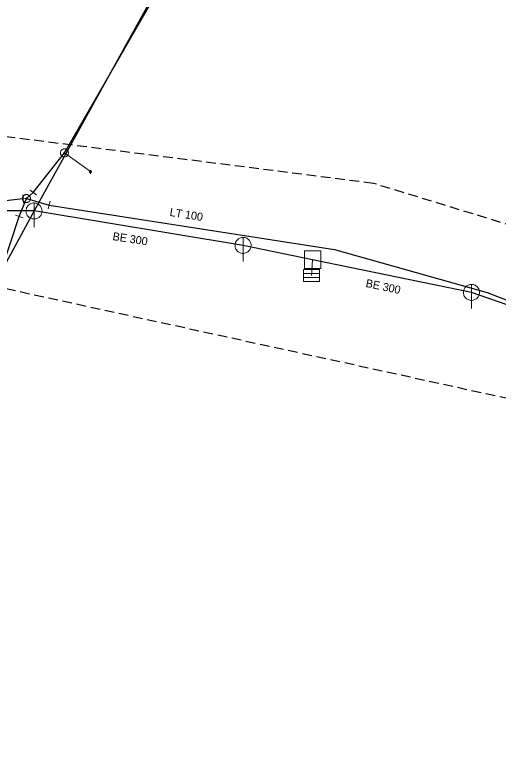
# Model space of a CAD drawing. Extents: x -687387 to -687009, y -972789 to -972578.
# Drawn here: x -687141.5 to -687081.2, y -972744.5 to -972651.8 of the extents above; entities that cross this region are included whole.
import ezdxf

# ---------------------------------------------------------------- set-up
doc = ezdxf.new("R2010")
doc.units = 0
doc.header["$LTSCALE"] = 0.4
doc.linetypes.add('MEDIUM_DASHED', pattern=[4.5, 3, -1.5])
doc.layers.add('1', color=7, linetype='Continuous')
for name, color, linetype, lineweight in [('11', 7, 'Continuous', 13), ('14', 7, 'Continuous', 25), ('17', 7, 'Continuous', 25), ('22', 7, 'Continuous', 13), ('34', 7, 'Continuous', 13), ('47', 7, 'Continuous', 13), ('63', 7, 'MEDIUM_DASHED', 25), ('9', 7, 'Continuous', 13)]:
    doc.layers.add(name, color=color, linetype=linetype, lineweight=lineweight)

msp = doc.modelspace()

# ---------------------------------------------------------------- linework, layer by layer
at = {"layer": '11'}
msp.add_line((-687104.473, -972684.315), (-687104.363, -972682.335), dxfattribs=at)
at = {"layer": '14', "lineweight": 13}
for p, q in [((-687132.046, -972671.358), (-687135.293, -972669.02)), ((-687140.419, -972674.734), (-687140.013, -972674.707))]:
    msp.add_line(p, q, dxfattribs=at)
at = {"layer": '14'}
for p, q in [((-687139.074, -972676.263), (-687177.589, -972676.2)), ((-687113.022, -972680.553), (-687139.074, -972676.263)), ((-687104.363, -972682.335), (-687113.022, -972680.553)), ((-687084.556, -972686.414), (-687104.363, -972682.335)), ((-687076.354, -972689.285), (-687084.556, -972686.414))]:
    msp.add_line(p, q, dxfattribs=at)
for points in [[(-687109.862, -972623.402), (-687127.339, -972655.027), (-687139.074, -972676.263)], [(-687139.074, -972676.263), (-687143.356, -972684.136), (-687154.625, -972704.857), (-687159.462, -972713.752)]]:
    msp.add_lwpolyline(points, dxfattribs=at)
at = {"layer": '17'}
for p, q in [((-687139.168, -972673.949), (-687135.293, -972669.02)), ((-687140.013, -972674.707), (-687137.189, -972675.528))]:
    msp.add_line(p, q, dxfattribs=at)
for points in [[(-687135.293, -972669.02), (-687122.188, -972646.265), (-687104.355, -972614.76), (-687083.126, -972578.198)], [(-687175.65, -972744.492), (-687175.739, -972743.912), (-687173.329, -972740.07), (-687156.205, -972711.508), (-687144.176, -972686.673), (-687140.919, -972676.959), (-687140.013, -972674.707), (-687139.168, -972673.949)], [(-687140.419, -972674.734), (-687161.655, -972677.153), (-687161.956, -972677.145), (-687194.054, -972677.975), (-687218.609, -972681.129), (-687239.739, -972685.945)], [(-687137.189, -972675.528), (-687101.625, -972681.079), (-687082.6, -972686.438), (-687052.118, -972698.285)]]:
    msp.add_lwpolyline(points, dxfattribs=at)
at = {"layer": '22'}
for p, q in [((-687139.074, -972678.263), (-687139.073, -972675.263)), ((-687113.022, -972682.553), (-687113.021, -972679.553)), ((-687105.484, -972684.058), (-687103.484, -972684.058)), ((-687105.484, -972684.558), (-687103.484, -972684.558)), ((-687084.556, -972688.414), (-687084.555, -972685.414))]:
    msp.add_line(p, q, dxfattribs=at)
for points in [[(-687138.074, -972676.263), (-687138.079, -972676.154), (-687138.097, -972676.046), (-687138.127, -972675.94), (-687138.167, -972675.839), (-687138.219, -972675.742), (-687138.281, -972675.652), (-687138.353, -972675.569), (-687138.433, -972675.495), (-687138.521, -972675.429), (-687138.615, -972675.374), (-687138.715, -972675.329), (-687138.82, -972675.296), (-687138.927, -972675.274), (-687139.036, -972675.264), (-687139.146, -972675.266), (-687139.254, -972675.28), (-687139.361, -972675.305), (-687139.464, -972675.342), (-687139.562, -972675.391), (-687139.654, -972675.449), (-687139.74, -972675.518), (-687139.817, -972675.595), (-687139.886, -972675.681), (-687139.945, -972675.773), (-687139.993, -972675.871), (-687140.03, -972675.974), (-687140.056, -972676.081), (-687140.07, -972676.189), (-687140.073, -972676.299), (-687140.063, -972676.408), (-687140.042, -972676.515), (-687140.008, -972676.619), (-687139.964, -972676.719), (-687139.909, -972676.814), (-687139.843, -972676.902), (-687139.769, -972676.982), (-687139.686, -972677.054), (-687139.596, -972677.116), (-687139.5, -972677.168), (-687139.398, -972677.209), (-687139.293, -972677.239), (-687139.185, -972677.257), (-687139.075, -972677.263), (-687138.966, -972677.257), (-687138.858, -972677.239), (-687138.753, -972677.21), (-687138.651, -972677.169), (-687138.554, -972677.117), (-687138.464, -972677.055), (-687138.381, -972676.984), (-687138.306, -972676.904), (-687138.241, -972676.816), (-687138.185, -972676.722), (-687138.141, -972676.622), (-687138.107, -972676.518), (-687138.085, -972676.41), (-687138.075, -972676.301)], [(-687112.022, -972680.553), (-687112.027, -972680.444), (-687112.045, -972680.336), (-687112.075, -972680.23), (-687112.115, -972680.129), (-687112.167, -972680.032), (-687112.229, -972679.942), (-687112.301, -972679.859), (-687112.381, -972679.785), (-687112.469, -972679.719), (-687112.563, -972679.664), (-687112.663, -972679.619), (-687112.768, -972679.586), (-687112.875, -972679.564), (-687112.984, -972679.554), (-687113.094, -972679.556), (-687113.202, -972679.57), (-687113.309, -972679.595), (-687113.412, -972679.632), (-687113.51, -972679.681), (-687113.602, -972679.739), (-687113.688, -972679.808), (-687113.765, -972679.885), (-687113.834, -972679.971), (-687113.893, -972680.063), (-687113.941, -972680.161), (-687113.978, -972680.264), (-687114.004, -972680.371), (-687114.018, -972680.479), (-687114.021, -972680.589), (-687114.011, -972680.698), (-687113.99, -972680.805), (-687113.956, -972680.909), (-687113.912, -972681.009), (-687113.857, -972681.104), (-687113.791, -972681.192), (-687113.717, -972681.272), (-687113.634, -972681.344), (-687113.544, -972681.406), (-687113.448, -972681.458), (-687113.346, -972681.499), (-687113.241, -972681.529), (-687113.133, -972681.547), (-687113.023, -972681.553), (-687112.914, -972681.547), (-687112.806, -972681.529), (-687112.701, -972681.5), (-687112.599, -972681.459), (-687112.502, -972681.407), (-687112.412, -972681.345), (-687112.329, -972681.274), (-687112.254, -972681.194), (-687112.189, -972681.106), (-687112.133, -972681.012), (-687112.089, -972680.912), (-687112.055, -972680.808), (-687112.033, -972680.7), (-687112.023, -972680.591)], [(-687105.343, -972681.245), (-687103.31, -972681.245), (-687103.31, -972683.438), (-687105.343, -972683.438)], [(-687105.484, -972683.558), (-687103.484, -972683.558), (-687103.484, -972685.058), (-687105.484, -972685.058)], [(-687083.556, -972686.414), (-687083.561, -972686.305), (-687083.579, -972686.197), (-687083.609, -972686.091), (-687083.649, -972685.99), (-687083.701, -972685.893), (-687083.763, -972685.803), (-687083.835, -972685.72), (-687083.915, -972685.646), (-687084.003, -972685.58), (-687084.097, -972685.525), (-687084.197, -972685.48), (-687084.302, -972685.447), (-687084.409, -972685.425), (-687084.518, -972685.415), (-687084.628, -972685.417), (-687084.736, -972685.431), (-687084.843, -972685.456), (-687084.946, -972685.493), (-687085.044, -972685.542), (-687085.136, -972685.6), (-687085.222, -972685.669), (-687085.299, -972685.746), (-687085.368, -972685.832), (-687085.427, -972685.924), (-687085.475, -972686.022), (-687085.512, -972686.125), (-687085.538, -972686.232), (-687085.552, -972686.34), (-687085.555, -972686.45), (-687085.545, -972686.559), (-687085.524, -972686.666), (-687085.49, -972686.77), (-687085.446, -972686.87), (-687085.391, -972686.965), (-687085.325, -972687.053), (-687085.251, -972687.133), (-687085.168, -972687.205), (-687085.078, -972687.267), (-687084.982, -972687.319), (-687084.88, -972687.36), (-687084.775, -972687.39), (-687084.667, -972687.408), (-687084.557, -972687.414), (-687084.448, -972687.408), (-687084.34, -972687.39), (-687084.235, -972687.361), (-687084.133, -972687.32), (-687084.036, -972687.268), (-687083.946, -972687.206), (-687083.863, -972687.135), (-687083.788, -972687.055), (-687083.723, -972686.967), (-687083.667, -972686.873), (-687083.623, -972686.773), (-687083.589, -972686.669), (-687083.567, -972686.561), (-687083.557, -972686.452)]]:
    msp.add_lwpolyline(points, close=True, dxfattribs=at)
at = {"layer": '34'}
for p, q in [((-687139.567, -972673.648), (-687138.768, -972674.249)), ((-687140.454, -972674.235), (-687140.384, -972675.232)), ((-687137.054, -972675.046), (-687137.324, -972676.009)), ((-687141.393, -972676.8), (-687140.444, -972677.118))]:
    msp.add_line(p, q, dxfattribs=at)
at = {"layer": '47'}
for points in [[(-687135.045, -972668.585), (-687135.091, -972668.562), (-687135.141, -972668.543), (-687135.191, -972668.531), (-687135.242, -972668.522), (-687135.295, -972668.52), (-687135.348, -972668.523), (-687135.399, -972668.532), (-687135.449, -972668.546), (-687135.498, -972668.564), (-687135.545, -972668.588), (-687135.589, -972668.617), (-687135.629, -972668.65), (-687135.666, -972668.687), (-687135.698, -972668.728), (-687135.727, -972668.772), (-687135.75, -972668.818), (-687135.769, -972668.868), (-687135.782, -972668.919), (-687135.79, -972668.969), (-687135.792, -972669.022), (-687135.789, -972669.075), (-687135.781, -972669.127), (-687135.767, -972669.177), (-687135.749, -972669.226), (-687135.724, -972669.272), (-687135.695, -972669.316), (-687135.662, -972669.357), (-687135.625, -972669.393), (-687135.584, -972669.425), (-687135.54, -972669.454), (-687135.494, -972669.477), (-687135.444, -972669.496), (-687135.394, -972669.51), (-687135.343, -972669.517), (-687135.29, -972669.519), (-687135.238, -972669.517), (-687135.186, -972669.509), (-687135.135, -972669.495), (-687135.086, -972669.476), (-687135.04, -972669.451), (-687134.996, -972669.422), (-687134.956, -972669.39), (-687134.919, -972669.352), (-687134.887, -972669.311), (-687134.858, -972669.267), (-687134.835, -972669.221), (-687134.816, -972669.171), (-687134.803, -972669.121), (-687134.795, -972669.07), (-687134.793, -972669.017), (-687134.795, -972668.965), (-687134.804, -972668.914), (-687134.818, -972668.863), (-687134.837, -972668.814), (-687134.861, -972668.767), (-687134.89, -972668.723), (-687134.923, -972668.684), (-687134.96, -972668.646), (-687135.001, -972668.614)], [(-687135.252, -972668.948), (-687135.26, -972668.944), (-687135.268, -972668.942), (-687135.276, -972668.939), (-687135.284, -972668.938), (-687135.293, -972668.938), (-687135.302, -972668.938), (-687135.31, -972668.939), (-687135.318, -972668.942), (-687135.326, -972668.945), (-687135.334, -972668.949), (-687135.341, -972668.954), (-687135.348, -972668.959), (-687135.354, -972668.965), (-687135.359, -972668.971), (-687135.364, -972668.979), (-687135.368, -972668.987), (-687135.37, -972668.995), (-687135.373, -972669.003), (-687135.374, -972669.011), (-687135.374, -972669.02), (-687135.374, -972669.029), (-687135.373, -972669.037), (-687135.37, -972669.045), (-687135.367, -972669.054), (-687135.363, -972669.061), (-687135.358, -972669.068), (-687135.353, -972669.075), (-687135.347, -972669.081), (-687135.341, -972669.086), (-687135.333, -972669.091), (-687135.325, -972669.095), (-687135.317, -972669.097), (-687135.309, -972669.1), (-687135.301, -972669.101), (-687135.292, -972669.101), (-687135.284, -972669.101), (-687135.275, -972669.1), (-687135.267, -972669.097), (-687135.258, -972669.094), (-687135.251, -972669.09), (-687135.244, -972669.085), (-687135.237, -972669.08), (-687135.231, -972669.074), (-687135.226, -972669.068), (-687135.221, -972669.06), (-687135.217, -972669.052), (-687135.215, -972669.044), (-687135.212, -972669.036), (-687135.211, -972669.028), (-687135.211, -972669.019), (-687135.211, -972669.011), (-687135.212, -972669.002), (-687135.215, -972668.994), (-687135.218, -972668.986), (-687135.222, -972668.978), (-687135.227, -972668.971), (-687135.232, -972668.964), (-687135.238, -972668.958), (-687135.244, -972668.953)], [(-687139.513, -972674.678), (-687139.519, -972674.626), (-687139.53, -972674.575), (-687139.547, -972674.526), (-687139.568, -972674.478), (-687139.595, -972674.432), (-687139.626, -972674.39), (-687139.661, -972674.352), (-687139.7, -972674.317), (-687139.742, -972674.286), (-687139.788, -972674.26), (-687139.836, -972674.239), (-687139.886, -972674.223), (-687139.937, -972674.212), (-687139.989, -972674.207), (-687140.041, -972674.207), (-687140.093, -972674.213), (-687140.144, -972674.224), (-687140.194, -972674.241), (-687140.241, -972674.262), (-687140.287, -972674.289), (-687140.329, -972674.32), (-687140.368, -972674.355), (-687140.403, -972674.394), (-687140.434, -972674.436), (-687140.459, -972674.482), (-687140.48, -972674.53), (-687140.497, -972674.58), (-687140.507, -972674.631), (-687140.512, -972674.683), (-687140.512, -972674.735), (-687140.506, -972674.787), (-687140.495, -972674.838), (-687140.479, -972674.888), (-687140.457, -972674.935), (-687140.43, -972674.981), (-687140.4, -972675.023), (-687140.365, -972675.062), (-687140.326, -972675.097), (-687140.283, -972675.128), (-687140.237, -972675.153), (-687140.189, -972675.174), (-687140.14, -972675.191), (-687140.088, -972675.201), (-687140.036, -972675.206), (-687139.984, -972675.206), (-687139.932, -972675.2), (-687139.881, -972675.189), (-687139.832, -972675.173), (-687139.784, -972675.151), (-687139.738, -972675.124), (-687139.696, -972675.094), (-687139.658, -972675.059), (-687139.623, -972675.02), (-687139.592, -972674.977), (-687139.566, -972674.931), (-687139.545, -972674.883), (-687139.529, -972674.834), (-687139.518, -972674.782), (-687139.513, -972674.73)], [(-687139.931, -972674.702), (-687139.931, -972674.693), (-687139.934, -972674.685), (-687139.936, -972674.677), (-687139.94, -972674.669), (-687139.944, -972674.662), (-687139.949, -972674.655), (-687139.955, -972674.648), (-687139.961, -972674.642), (-687139.968, -972674.638), (-687139.976, -972674.633), (-687139.984, -972674.63), (-687139.992, -972674.627), (-687140, -972674.626), (-687140.008, -972674.624), (-687140.017, -972674.625), (-687140.026, -972674.625), (-687140.034, -972674.628), (-687140.042, -972674.63), (-687140.05, -972674.634), (-687140.057, -972674.638), (-687140.064, -972674.643), (-687140.071, -972674.649), (-687140.077, -972674.655), (-687140.082, -972674.662), (-687140.086, -972674.67), (-687140.089, -972674.678), (-687140.092, -972674.686), (-687140.093, -972674.694), (-687140.095, -972674.702), (-687140.094, -972674.711), (-687140.094, -972674.72), (-687140.091, -972674.728), (-687140.089, -972674.736), (-687140.085, -972674.744), (-687140.081, -972674.751), (-687140.077, -972674.758), (-687140.07, -972674.765), (-687140.064, -972674.771), (-687140.057, -972674.776), (-687140.049, -972674.78), (-687140.041, -972674.783), (-687140.033, -972674.786), (-687140.025, -972674.787), (-687140.017, -972674.789), (-687140.008, -972674.788), (-687139.999, -972674.788), (-687139.991, -972674.785), (-687139.983, -972674.783), (-687139.975, -972674.779), (-687139.968, -972674.775), (-687139.961, -972674.771), (-687139.954, -972674.764), (-687139.948, -972674.758), (-687139.944, -972674.751), (-687139.939, -972674.743), (-687139.936, -972674.735), (-687139.933, -972674.727), (-687139.932, -972674.719), (-687139.93, -972674.711)]]:
    msp.add_lwpolyline(points, close=True, dxfattribs=at)
at = {"layer": '63'}
msp.add_lwpolyline([(-687198.94, -972690.124), (-687142.558, -972685.938), (-687142.558, -972685.938), (-687071.103, -972701.568), (-687071.103, -972701.568), (-687078.081, -972717.199), (-687078.081, -972717.199), (-687052.96, -972718.874), (-687052.96, -972718.874), (-687039.004, -972700.731), (-687039.004, -972700.731), (-687036.212, -972687.333), (-687036.212, -972687.333), (-687054.635, -972678.68), (-687054.635, -972678.68), (-687058.542, -972684.542), (-687058.542, -972684.542), (-687096.782, -972672.819), (-687096.782, -972672.819), (-687147.303, -972666.399), (-687147.303, -972666.399), (-687234.11, -972667.795)], dxfattribs=at)
at = {"layer": '9'}
msp.add_line((-687132.047, -972671.485), (-687132.047, -972671.61), dxfattribs=at)
for points in [[(-687132.173, -972671.357), (-687132.172, -972671.37), (-687132.17, -972671.383), (-687132.167, -972671.396), (-687132.162, -972671.408), (-687132.156, -972671.42), (-687132.149, -972671.431), (-687132.141, -972671.441), (-687132.131, -972671.451), (-687132.121, -972671.459), (-687132.11, -972671.466), (-687132.098, -972671.472), (-687132.086, -972671.477), (-687132.073, -972671.48), (-687132.06, -972671.482), (-687132.047, -972671.485), (-687132.034, -972671.484), (-687132.021, -972671.482), (-687132.008, -972671.479), (-687131.996, -972671.474), (-687131.984, -972671.468), (-687131.973, -972671.461), (-687131.963, -972671.453), (-687131.953, -972671.443), (-687131.945, -972671.433), (-687131.938, -972671.422), (-687131.932, -972671.41), (-687131.927, -972671.398), (-687131.924, -972671.385), (-687131.922, -972671.372), (-687131.92, -972671.359), (-687131.921, -972671.346), (-687131.923, -972671.333), (-687131.926, -972671.32), (-687131.931, -972671.308), (-687131.937, -972671.296), (-687131.944, -972671.285), (-687131.952, -972671.275), (-687131.962, -972671.265), (-687131.972, -972671.257), (-687131.983, -972671.25), (-687131.995, -972671.244), (-687132.007, -972671.239), (-687132.02, -972671.236), (-687132.033, -972671.234), (-687132.046, -972671.232), (-687132.059, -972671.232), (-687132.072, -972671.234), (-687132.085, -972671.237), (-687132.097, -972671.242), (-687132.109, -972671.248), (-687132.12, -972671.255), (-687132.13, -972671.263), (-687132.14, -972671.273), (-687132.148, -972671.283), (-687132.155, -972671.294), (-687132.161, -972671.306), (-687132.166, -972671.318), (-687132.169, -972671.331), (-687132.171, -972671.344)], [(-687132.153, -972671.357), (-687132.153, -972671.368), (-687132.151, -972671.379), (-687132.148, -972671.39), (-687132.144, -972671.4), (-687132.139, -972671.41), (-687132.133, -972671.419), (-687132.126, -972671.428), (-687132.118, -972671.436), (-687132.109, -972671.443), (-687132.1, -972671.449), (-687132.09, -972671.454), (-687132.08, -972671.458), (-687132.069, -972671.461), (-687132.058, -972671.463), (-687132.047, -972671.463), (-687132.036, -972671.465), (-687132.025, -972671.463), (-687132.014, -972671.46), (-687132.004, -972671.456), (-687131.994, -972671.451), (-687131.985, -972671.445), (-687131.976, -972671.438), (-687131.968, -972671.43), (-687131.961, -972671.421), (-687131.955, -972671.412), (-687131.95, -972671.402), (-687131.946, -972671.392), (-687131.943, -972671.381), (-687131.941, -972671.37), (-687131.94, -972671.359), (-687131.94, -972671.348), (-687131.942, -972671.337), (-687131.945, -972671.326), (-687131.949, -972671.316), (-687131.954, -972671.306), (-687131.96, -972671.297), (-687131.967, -972671.288), (-687131.975, -972671.28), (-687131.984, -972671.273), (-687131.993, -972671.267), (-687132.003, -972671.262), (-687132.013, -972671.258), (-687132.024, -972671.255), (-687132.035, -972671.253), (-687132.046, -972671.252), (-687132.057, -972671.251), (-687132.068, -972671.253), (-687132.079, -972671.256), (-687132.089, -972671.26), (-687132.099, -972671.265), (-687132.108, -972671.271), (-687132.117, -972671.278), (-687132.125, -972671.286), (-687132.132, -972671.295), (-687132.138, -972671.304), (-687132.143, -972671.314), (-687132.147, -972671.324), (-687132.15, -972671.335), (-687132.152, -972671.346)], [(-687132.134, -972671.357), (-687132.133, -972671.366), (-687132.132, -972671.375), (-687132.129, -972671.384), (-687132.126, -972671.392), (-687132.122, -972671.4), (-687132.117, -972671.408), (-687132.111, -972671.415), (-687132.105, -972671.421), (-687132.098, -972671.427), (-687132.09, -972671.432), (-687132.082, -972671.436), (-687132.074, -972671.439), (-687132.065, -972671.442), (-687132.056, -972671.443), (-687132.047, -972671.446), (-687132.038, -972671.445), (-687132.029, -972671.444), (-687132.02, -972671.441), (-687132.012, -972671.438), (-687132.004, -972671.434), (-687131.996, -972671.429), (-687131.989, -972671.423), (-687131.983, -972671.417), (-687131.977, -972671.41), (-687131.972, -972671.402), (-687131.968, -972671.394), (-687131.965, -972671.386), (-687131.962, -972671.377), (-687131.961, -972671.368), (-687131.959, -972671.359), (-687131.96, -972671.35), (-687131.961, -972671.341), (-687131.964, -972671.332), (-687131.967, -972671.324), (-687131.971, -972671.316), (-687131.976, -972671.308), (-687131.982, -972671.301), (-687131.988, -972671.295), (-687131.995, -972671.289), (-687132.003, -972671.284), (-687132.011, -972671.28), (-687132.019, -972671.277), (-687132.028, -972671.274), (-687132.037, -972671.273), (-687132.046, -972671.271), (-687132.055, -972671.271), (-687132.064, -972671.272), (-687132.073, -972671.275), (-687132.081, -972671.278), (-687132.089, -972671.282), (-687132.097, -972671.287), (-687132.104, -972671.293), (-687132.11, -972671.299), (-687132.116, -972671.306), (-687132.121, -972671.314), (-687132.125, -972671.322), (-687132.128, -972671.33), (-687132.131, -972671.339), (-687132.132, -972671.348)], [(-687132.114, -972671.357), (-687132.114, -972671.364), (-687132.112, -972671.371), (-687132.111, -972671.378), (-687132.108, -972671.384), (-687132.105, -972671.39), (-687132.101, -972671.396), (-687132.097, -972671.402), (-687132.092, -972671.407), (-687132.086, -972671.411), (-687132.08, -972671.415), (-687132.074, -972671.418), (-687132.068, -972671.421), (-687132.061, -972671.422), (-687132.054, -972671.424), (-687132.047, -972671.424), (-687132.04, -972671.426), (-687132.033, -972671.424), (-687132.026, -972671.423), (-687132.02, -972671.42), (-687132.013, -972671.417), (-687132.008, -972671.413), (-687132.002, -972671.409), (-687131.997, -972671.404), (-687131.993, -972671.398), (-687131.989, -972671.392), (-687131.986, -972671.386), (-687131.983, -972671.38), (-687131.981, -972671.373), (-687131.98, -972671.366), (-687131.979, -972671.359), (-687131.979, -972671.352), (-687131.98, -972671.345), (-687131.982, -972671.338), (-687131.985, -972671.332), (-687131.988, -972671.325), (-687131.992, -972671.32), (-687131.996, -972671.314), (-687132.001, -972671.309), (-687132.007, -972671.305), (-687132.012, -972671.301), (-687132.019, -972671.298), (-687132.025, -972671.295), (-687132.032, -972671.293), (-687132.039, -972671.292), (-687132.046, -972671.291), (-687132.053, -972671.29), (-687132.06, -972671.291), (-687132.067, -972671.293), (-687132.073, -972671.296), (-687132.079, -972671.299), (-687132.085, -972671.303), (-687132.091, -972671.307), (-687132.096, -972671.312), (-687132.1, -972671.318), (-687132.104, -972671.323), (-687132.107, -972671.33), (-687132.11, -972671.336), (-687132.111, -972671.343), (-687132.113, -972671.35)], [(-687132.094, -972671.357), (-687132.094, -972671.362), (-687132.093, -972671.367), (-687132.092, -972671.372), (-687132.09, -972671.376), (-687132.088, -972671.381), (-687132.085, -972671.385), (-687132.082, -972671.388), (-687132.078, -972671.392), (-687132.075, -972671.395), (-687132.071, -972671.398), (-687132.066, -972671.4), (-687132.062, -972671.402), (-687132.057, -972671.403), (-687132.052, -972671.404), (-687132.047, -972671.404), (-687132.042, -972671.406), (-687132.037, -972671.405), (-687132.032, -972671.404), (-687132.028, -972671.402), (-687132.023, -972671.4), (-687132.019, -972671.397), (-687132.015, -972671.394), (-687132.012, -972671.39), (-687132.009, -972671.387), (-687132.006, -972671.383), (-687132.004, -972671.378), (-687132.002, -972671.374), (-687132.001, -972671.369), (-687132, -972671.364), (-687132, -972671.359), (-687131.999, -972671.354), (-687132, -972671.349), (-687132.001, -972671.344), (-687132.003, -972671.34), (-687132.005, -972671.335), (-687132.008, -972671.331), (-687132.011, -972671.327), (-687132.014, -972671.324), (-687132.018, -972671.321), (-687132.022, -972671.318), (-687132.027, -972671.316), (-687132.031, -972671.314), (-687132.036, -972671.313), (-687132.041, -972671.312), (-687132.046, -972671.311), (-687132.051, -972671.31), (-687132.056, -972671.311), (-687132.061, -972671.312), (-687132.065, -972671.314), (-687132.07, -972671.316), (-687132.074, -972671.319), (-687132.077, -972671.322), (-687132.081, -972671.325), (-687132.084, -972671.329), (-687132.087, -972671.333), (-687132.089, -972671.338), (-687132.091, -972671.342), (-687132.092, -972671.347), (-687132.093, -972671.352)], [(-687132.074, -972671.357), (-687132.074, -972671.36), (-687132.074, -972671.363), (-687132.073, -972671.365), (-687132.072, -972671.368), (-687132.071, -972671.371), (-687132.069, -972671.373), (-687132.067, -972671.375), (-687132.065, -972671.377), (-687132.063, -972671.379), (-687132.061, -972671.381), (-687132.058, -972671.382), (-687132.055, -972671.383), (-687132.053, -972671.384), (-687132.05, -972671.384), (-687132.047, -972671.384), (-687132.044, -972671.386), (-687132.041, -972671.386), (-687132.038, -972671.385), (-687132.036, -972671.384), (-687132.033, -972671.383), (-687132.031, -972671.381), (-687132.028, -972671.379), (-687132.026, -972671.377), (-687132.025, -972671.375), (-687132.023, -972671.373), (-687132.022, -972671.37), (-687132.021, -972671.367), (-687132.02, -972671.365), (-687132.02, -972671.362), (-687132.018, -972671.359), (-687132.019, -972671.356), (-687132.019, -972671.353), (-687132.02, -972671.35), (-687132.021, -972671.348), (-687132.022, -972671.345), (-687132.024, -972671.343), (-687132.025, -972671.34), (-687132.027, -972671.338), (-687132.03, -972671.337), (-687132.032, -972671.335), (-687132.035, -972671.334), (-687132.037, -972671.333), (-687132.04, -972671.332), (-687132.043, -972671.332), (-687132.046, -972671.33), (-687132.049, -972671.33), (-687132.052, -972671.33), (-687132.054, -972671.331), (-687132.057, -972671.332), (-687132.06, -972671.333), (-687132.062, -972671.335), (-687132.064, -972671.336), (-687132.066, -972671.338), (-687132.068, -972671.341), (-687132.07, -972671.343), (-687132.071, -972671.346), (-687132.072, -972671.348), (-687132.073, -972671.351), (-687132.073, -972671.354)], [(-687132.055, -972671.357), (-687132.055, -972671.358), (-687132.055, -972671.359), (-687132.054, -972671.359), (-687132.054, -972671.36), (-687132.054, -972671.361), (-687132.053, -972671.362), (-687132.053, -972671.362), (-687132.052, -972671.363), (-687132.052, -972671.363), (-687132.051, -972671.364), (-687132.05, -972671.364), (-687132.049, -972671.364), (-687132.049, -972671.365), (-687132.048, -972671.365), (-687132.047, -972671.365), (-687132.046, -972671.366), (-687132.045, -972671.366), (-687132.045, -972671.366), (-687132.044, -972671.366), (-687132.043, -972671.366), (-687132.042, -972671.365), (-687132.042, -972671.365), (-687132.041, -972671.364), (-687132.041, -972671.364), (-687132.04, -972671.363), (-687132.04, -972671.362), (-687132.039, -972671.361), (-687132.039, -972671.361), (-687132.039, -972671.36), (-687132.038, -972671.359), (-687132.038, -972671.358), (-687132.038, -972671.357), (-687132.038, -972671.357), (-687132.039, -972671.356), (-687132.039, -972671.355), (-687132.04, -972671.354), (-687132.04, -972671.354), (-687132.041, -972671.353), (-687132.041, -972671.353), (-687132.042, -972671.352), (-687132.043, -972671.352), (-687132.044, -972671.351), (-687132.044, -972671.351), (-687132.045, -972671.351), (-687132.046, -972671.35), (-687132.047, -972671.35), (-687132.048, -972671.349), (-687132.048, -972671.349), (-687132.049, -972671.35), (-687132.05, -972671.35), (-687132.051, -972671.351), (-687132.051, -972671.351), (-687132.052, -972671.352), (-687132.052, -972671.352), (-687132.053, -972671.353), (-687132.053, -972671.354), (-687132.053, -972671.355), (-687132.054, -972671.355), (-687132.054, -972671.356)]]:
    msp.add_lwpolyline(points, close=True, dxfattribs=at)
msp.add_lwpolyline([(-687132.016, -972671.576), (-687132.047, -972671.61), (-687132.078, -972671.574)], dxfattribs=at)

# ---------------------------------------------------------------- texts
at = {"layer": '1'}
for s, rotation, p in [('LT 100', 351, (-687122.219, -972676.867)), ('BE 300', 351, (-687129.331, -972679.878)), ('BE 300', 348, (-687097.798, -972685.713))]:
    msp.add_text(s, height=1, rotation=rotation, dxfattribs=at).set_placement(p)

doc.saveas('drawing.dxf')
